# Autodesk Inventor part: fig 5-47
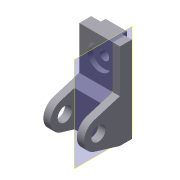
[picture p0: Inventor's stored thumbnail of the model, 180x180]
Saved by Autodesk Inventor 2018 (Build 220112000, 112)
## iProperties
Shininess: 65.0
Angle Display Precision: 2
Document Length Units: 11269
Document Angle Units: 11279
Document Time Units: 11290
Document Mass Units: 11283
Document Length Units Precision: 3
Document Angle Units Precision: 2
Created: 2001-11
Part Number: fig 5-47
Document SubType Name: Modeling
Designer: Renu Muthoo
Density: 1 g/cm^3
Material: Generic
Appearance: Aluminum - Flat
Density: 0.0
Volumn: 0.0
Area: 0.0
PropertySet Name: Model Information
Control State: 0
Master: False
Checked Out: False
Author: Renu Muthoo
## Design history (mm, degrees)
node "Sketch1"
sketch "Sketch2"
  geometry: L1 (33.257, 104.664)-(33.257, -75.336); L2 (33.257, -75.336)-(8.257, -75.336); L3 (8.257, -75.336)-(-45.451, -59.045); L4 (-45.451, -1.628)-(8.257, 14.664); L5 (8.257, 14.664)-(8.257, 104.664); L6 (8.257, 104.664)-(33.257, 104.664); C1 r 15 at (-36.743, -30.336); A1 r 30 centre (-36.743, -30.336) between (-45.451, -1.628) and (-45.451, -59.045)
  constraints: 12 end point, 2 centre point, 2 equal length, 2 parallel, 2 point on circle, 2 tangent, 1 coincident, 1 perpendicular, 1 vertical
  dimensions: "d0" = 180 distance of L1.start L1.end; "d1" = 30 radius of A1; "d2" = 25 distance of L5.end L1.start; "d3" = 45 distance from line of L2 A1.centre; "d4" = 70 distance from line of L1 A1.centre; "d5" = 30 diameter of C1
extrude "Extrusion1" new body sketch "Sketch2" distance "d6" = 85; taper "d7" = 0 deg
workplane "Work Plane1"
sketch "Sketch3"
  geometry: L1 (15, 62.364)-(70, 62.364); L2 (70, 62.364)-(70, -52.386); L3 (70, -52.386)-(15, -52.386); L4 (15, -52.386)-(15, 62.364); L5 (0, -45)-(0, -28.708) reference
  constraints: 8 end point, 2 parallel, 1 horizontal, 1 perpendicular
  dimensions: "d8" = 55 distance of L1.start L1.end; "d9" = 15 distance between parallel lines of L5 L4
extrude "Extrusion2" cut sketch "Sketch3" distance "d10" = 50; taper "d11" = 0 deg
sketch "Sketch4"
  geometry: L1 (0, 25)-(85, 25) reference; L2 (0, 0)-(0, 25) reference; L3 (20, 25)-(65, 25); L4 (65, 25)-(65, 35); L5 (65, 35)-(20, 35); L6 (20, 35)-(20, 25)
  constraints: 8 end point, 2 parallel, 1 horizontal, 1 perpendicular, 1 point on line
  dimensions: "d12" = 45 distance of L4.end L5.end; "d13" = 10 distance of L3.end L4.end; "d14" = 20 distance between parallel lines of L2 L6
extrude "Extrusion3" join sketch "Sketch4" stored distance "d15" = 50; taper "d16" = 0 deg
sketch "Sketch5"
  geometry: L1 (85, 0)-(85, 90) reference; L2 (0, 90)-(85, 90) reference; 1 further point
  dimensions: "d17" = 42 distance from line of L2 point (42.5, 48); "d18" = 42.5 distance from line of L1 point (42.5, 48)
hole "Hole1" sketch "Sketch5" at (42.5, 48) diameter "d19" = 20; stored, may be unused: countersink angle "d23" = 82 deg, drill point angle "d25" = 118 deg; dims "d20" = 6, "d21" = 50, "d22" = 10, "d24" = 8
workplane "Work Plane7"
workpoint "Work Point7"
workpoint "Work Point8"
body "Solid1"
other parameters: "d29" = 0
